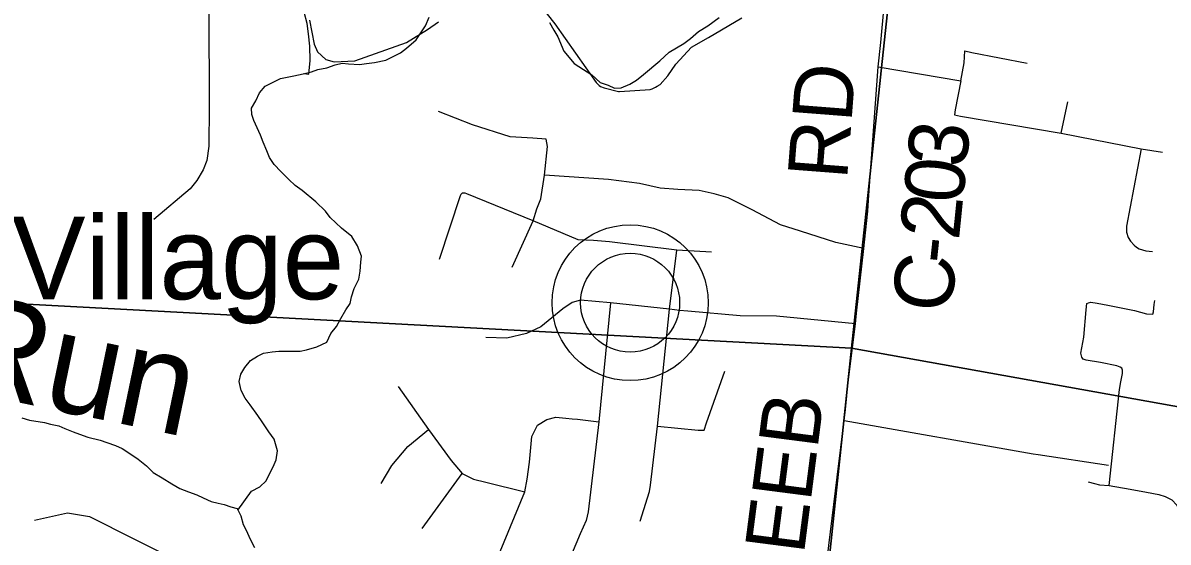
# Model space of a CAD drawing. Extents: x 0 to 34, y -2 to 22.
# Drawn here: x 3.329 to 4.421, y 16.731 to 17.226 of the extents above; entities that cross this region are included whole.
import ezdxf

# ---------------------------------------------------------------- set-up
doc = ezdxf.new("R2010")
doc.units = 0
for name, color, linetype in [('GM_X_County_Road', 7, 'Continuous'), ('GM_X_County_Road_Text', 7, 'Continuous'), ('GM_X_Minor_River', 7, 'Continuous'), ('GM_X_Minor_River_Text', 7, 'Continuous'), ('GM_X_Section', 7, 'Continuous'), ('GM_X_Township_Road', 7, 'Continuous'), ('GM_X_Unincorporated', 7, 'Continuous'), ('GM_X_Unincorporated_Location', 7, 'Continuous'), ('GM_X_Unincorporated_Text', 7, 'Continuous')]:
    doc.layers.add(name, color=color, linetype=linetype)

msp = doc.modelspace()

# ---------------------------------------------------------------- linework, layer by layer
at = {"layer": 'GM_X_County_Road'}
for points in [[(4.1357, 17.0618), (4.1445, 17.1843), (4.147, 17.2076), (4.1533, 17.2738), (4.1587, 17.295), (4.1597, 17.3001), (4.1595, 17.3027), (4.1576, 17.3113), (4.1539, 17.3349), (4.1534, 17.3381), (4.1533, 17.3414), (4.1555, 17.3542), (4.171, 17.4373), (4.1756, 17.4751), (4.1791, 17.5032), (4.188, 17.5731), (4.2018, 17.6987), (4.2231, 17.8563)], [(3.8216, 17.2439), (3.8364, 17.2254), (3.8757, 17.1695), (3.8786, 17.1664), (3.8799, 17.1655), (3.8832, 17.1644), (3.897, 17.1609), (3.8979, 17.1607), (3.9271, 17.1627), (3.9291, 17.1633), (3.9323, 17.1648), (3.934, 17.1658), (3.9366, 17.1674), (3.9441, 17.1756), (3.9516, 17.1868), (3.9667, 17.2032), (3.9828, 17.2123), (4.0147, 17.231)], [(3.6024, 17.2289), (3.6069, 17.2061), (3.6101, 17.1988), (3.6179, 17.1914), (3.6258, 17.189), (3.6456, 17.1901), (3.6949, 17.2076), (3.7149, 17.22), (3.7253, 17.2274)], [(4.124, 16.9493), (4.131, 17.0108), (4.1346, 17.0465), (4.1357, 17.0618)], [(4.1133, 16.8573), (4.1161, 16.8832), (4.1229, 16.9391), (4.124, 16.9493)], [(4.1005, 16.5212), (4.1022, 16.532), (4.1001, 16.5438), (4.0993, 16.5618), (4.0889, 16.5904), (4.086, 16.6037), (4.0848, 16.6181), (4.0856, 16.6343), (4.0959, 16.7145), (4.1054, 16.7928), (4.1122, 16.8469), (4.1133, 16.8573)], [(3.3401, 16.7515), (3.3717, 16.7585), (3.3928, 16.755), (3.4349, 16.7339), (3.463, 16.7199), (3.5016, 16.6918), (3.5297, 16.6777), (3.5648, 16.6742), (3.6105, 16.6742), (3.6518, 16.6741)]]:
    msp.add_lwpolyline(points, dxfattribs=at)
at = {"layer": 'GM_X_Minor_River'}
for points in [[(3.5342, 16.7612), (3.5471, 16.7792), (3.5552, 16.7836), (3.561, 16.7892), (3.5641, 16.7952), (3.5677, 16.8027), (3.5705, 16.8091), (3.5718, 16.8179), (3.5686, 16.8289), (3.5637, 16.8359), (3.5574, 16.8455), (3.5533, 16.8516), (3.5459, 16.8617), (3.541, 16.8682), (3.5374, 16.8755), (3.5352, 16.8839), (3.5369, 16.8911), (3.5408, 16.8975), (3.5463, 16.9039), (3.5529, 16.9083), (3.5586, 16.9109), (3.5667, 16.9122), (3.5732, 16.9129), (3.58, 16.9128), (3.5858, 16.913), (3.5934, 16.9129), (3.5995, 16.9143), (3.6095, 16.9172), (3.6188, 16.9216), (3.6227, 16.9299), (3.6282, 16.9366), (3.6322, 16.9441), (3.6369, 16.9524), (3.6412, 16.9584), (3.6425, 16.9649), (3.6449, 16.9728), (3.6493, 16.9818), (3.6506, 16.9894), (3.6515, 16.9978), (3.652, 17.0035), (3.6483, 17.0134), (3.6428, 17.0223), (3.633, 17.0304), (3.6221, 17.0405), (3.6176, 17.0467), (3.6086, 17.0556), (3.5954, 17.0664), (3.5887, 17.0711), (3.5827, 17.0769), (3.5752, 17.0843), (3.5688, 17.0912), (3.5643, 17.0978), (3.5618, 17.1043), (3.5581, 17.1123), (3.5556, 17.1192), (3.5493, 17.133), (3.5475, 17.1388), (3.5472, 17.1448), (3.5512, 17.152), (3.5548, 17.1595), (3.5602, 17.1659), (3.5683, 17.1699), (3.5749, 17.1732), (3.5875, 17.1757), (3.5963, 17.1778), (3.6044, 17.1796), (3.6105, 17.1817), (3.619, 17.1835), (3.627, 17.1864), (3.6336, 17.1878), (3.6397, 17.1873), (3.65, 17.1867), (3.6568, 17.1874), (3.6645, 17.1884), (3.6752, 17.1908), (3.6814, 17.1938), (3.6891, 17.1978), (3.6949, 17.2023), (3.7042, 17.2101), (3.7129, 17.2236), (3.7165, 17.2319)], [(3.5969, 17.1779), (3.6019, 17.1775), (3.603, 17.1904), (3.6026, 17.204), (3.6014, 17.2158), (3.6001, 17.2258), (3.5973, 17.2365)], [(3.8313, 17.2268), (3.8354, 17.2195), (3.8391, 17.213), (3.8449, 17.1992), (3.8547, 17.1876), (3.8637, 17.1818), (3.8716, 17.1767), (3.8795, 17.1693), (3.8871, 17.1669), (3.8932, 17.1641), (3.8997, 17.1644), (3.9078, 17.1677), (3.9143, 17.1717), (3.9209, 17.1769), (3.9364, 17.19), (3.9454, 17.1982), (3.9523, 17.2026), (3.9593, 17.2067), (3.9655, 17.2115), (3.9732, 17.2182), (3.9821, 17.2234), (3.9929, 17.2315)], [(3.328, 16.8492), (3.3356, 16.8472), (3.3497, 16.845), (3.3554, 16.8434), (3.3634, 16.8417), (3.369, 16.839), (3.377, 16.8358), (3.3831, 16.8338), (3.3911, 16.831), (3.4028, 16.8281), (3.4093, 16.8257), (3.4176, 16.8229), (3.4237, 16.8201), (3.4312, 16.8154), (3.4392, 16.81), (3.4471, 16.8034), (3.4534, 16.7972), (3.4621, 16.7921), (3.4712, 16.7862), (3.4788, 16.7819), (3.4871, 16.7787), (3.4951, 16.7759), (3.5011, 16.7731), (3.5087, 16.7696), (3.5152, 16.7679), (3.5212, 16.7667), (3.5273, 16.7643), (3.5334, 16.7627), (3.5371, 16.7558), (3.5392, 16.7474), (3.5422, 16.7416), (3.5455, 16.734), (3.5499, 16.7255)]]:
    msp.add_lwpolyline(points, dxfattribs=at)
at = {"layer": 'GM_X_Section'}
for points in [[(4.2197, 17.8557), (4.1192, 16.9159), (3.2017, 16.9647), (3.2914, 17.96)], [(5.25, 17.7471), (5.1427, 16.732), (4.1192, 16.9159), (4.2197, 17.8557)], [(4.1192, 16.9159), (4.012, 15.9002), (3.2406, 16.0402), (3.231, 16.0514), (3.2225, 16.0599), (3.2118, 16.0701), (3.2044, 16.0774), (3.197, 16.0844), (3.1881, 16.0918), (3.1769, 16.1008), (3.1658, 16.1098), (3.1569, 16.1176), (3.1469, 16.1266), (3.1398, 16.1328), (3.1309, 16.1402), (3.1283, 16.1422), (3.2017, 16.9647)], [(5.1427, 16.732), (5.0363, 15.7105), (4.012, 15.9002), (4.1192, 16.9159)]]:
    msp.add_lwpolyline(points, close=True, dxfattribs=at)
at = {"layer": 'GM_X_Township_Road'}
for p, q in [((4.3191, 17.1211), (4.3255, 17.151)), ((4.297, 16.8142), (4.3641, 16.804)), ((3.7097, 16.7438), (3.7479, 16.7962))]:
    msp.add_line(p, q, dxfattribs=at)
for points in [[(3.5217, 17.3039), (3.5106, 17.2961), (3.506, 17.2775), (3.506, 17.2627), (3.5063, 17.2381), (3.5067, 17.1462), (3.5065, 17.1086), (3.5046, 17.095), (3.5009, 17.0859), (3.4949, 17.0758), (3.4886, 17.068), (3.4541, 17.0387)], [(4.2235, 17.171), (4.2266, 17.1881), (4.2272, 17.1996), (4.2338, 17.1981), (4.2866, 17.1877)], [(4.1445, 17.1843), (4.2235, 17.171), (4.2179, 17.1432), (4.2173, 17.1384), (4.223, 17.1374), (4.3191, 17.1211), (4.3953, 17.1061), (4.4155, 17.1028)], [(3.7957, 16.993), (3.8157, 17.0374), (3.8192, 17.0488), (3.8228, 17.0584), (3.8263, 17.0809), (3.8292, 17.1083), (3.8281, 17.1154), (3.8153, 17.1161), (3.7936, 17.1175), (3.7577, 17.1289), (3.7253, 17.1417)], [(4.3953, 17.1061), (4.3813, 17.0322), (4.3814, 17.0265), (4.383, 17.0215), (4.385, 17.018), (4.3887, 17.014), (4.3909, 17.0123), (4.3935, 17.0105), (4.3996, 17.0087), (4.4062, 17.008)], [(4.131, 17.0108), (4.1043, 17.0168), (4.0705, 17.0275), (4.0516, 17.0334), (4.0244, 17.0479), (4.0017, 17.0593), (3.9881, 17.0632), (3.974, 17.0663), (3.9537, 17.0673), (3.9368, 17.0686), (3.9169, 17.073), (3.8874, 17.0768), (3.8263, 17.0809)], [(3.9856, 17.0074), (3.9525, 17.0095), (3.8883, 17.0172), (3.8731, 17.0186), (3.8584, 17.0193), (3.8157, 17.0374), (3.7524, 17.063), (3.7509, 17.0636), (3.7493, 17.0639), (3.748, 17.0636), (3.7467, 17.0625), (3.7459, 17.0612), (3.726, 17.0006)], [(3.9177, 16.7506), (3.9246, 16.7728), (3.9264, 16.779), (3.9276, 16.7851), (3.9342, 16.8415), (3.9456, 16.9529), (3.9525, 17.0095)], [(3.9553, 16.9518), (3.9456, 16.9529), (3.8895, 16.9592), (3.8609, 16.9615), (3.8528, 16.9593), (3.8438, 16.9535), (3.823, 16.9362), (3.8093, 16.9298), (3.7904, 16.9254), (3.7705, 16.9259)], [(3.8895, 16.9592), (3.8781, 16.8455), (3.8682, 16.7597), (3.8661, 16.7514), (3.8605, 16.7386), (3.8301, 16.6657)], [(4.3649, 16.7846), (4.3748, 16.8765), (4.3759, 16.8837), (4.3776, 16.8916), (4.3774, 16.8949), (4.377, 16.8966), (4.3754, 16.8977), (4.3722, 16.8988), (4.3564, 16.9021), (4.343, 16.9043), (4.3401, 16.9054), (4.3388, 16.9072), (4.3379, 16.9111), (4.3408, 16.9263), (4.343, 16.9524), (4.3436, 16.9583), (4.345, 16.9592), (4.3474, 16.9596), (4.3533, 16.9587), (4.3634, 16.9567), (4.389, 16.9517), (4.4005, 16.9486), (4.4064, 16.9482), (4.407, 16.9506), (4.4077, 16.9576), (4.4083, 16.9613)], [(4.1229, 16.9391), (4.0475, 16.9465), (4.013, 16.9467), (3.9632, 16.951), (3.9553, 16.9518)], [(3.9342, 16.8415), (3.9731, 16.8375), (3.9786, 16.8375), (3.981, 16.8446), (3.9984, 16.8939)], [(3.6869, 16.8791), (3.7159, 16.8381), (3.7376, 16.8085), (3.7479, 16.7962), (3.7589, 16.7907), (3.7706, 16.788), (3.8077, 16.7786)], [(3.7783, 16.707), (3.8077, 16.7786), (3.8098, 16.7908), (3.8123, 16.8069), (3.8144, 16.8314), (3.8198, 16.8423), (3.8288, 16.8476), (3.8374, 16.8499), (3.8468, 16.849), (3.8529, 16.8484)], [(3.8529, 16.8484), (3.8578, 16.848), (3.8781, 16.8455)], [(4.1122, 16.8469), (4.2923, 16.8149), (4.297, 16.8142)], [(3.6708, 16.7867), (3.6809, 16.8039), (3.6963, 16.8219), (3.7159, 16.8381)], [(4.3447, 16.7881), (4.3507, 16.7865), (4.3557, 16.7854), (4.3649, 16.7846), (4.3847, 16.7811), (4.4005, 16.7784), (4.4121, 16.7762), (4.4182, 16.7743), (4.4244, 16.7712), (4.4292, 16.7661), (4.4344, 16.753), (4.4369, 16.7431), (4.4384, 16.7346), (4.4364, 16.7269), (4.4351, 16.7205), (4.4358, 16.7122), (4.4382, 16.7085), (4.4407, 16.704)]]:
    msp.add_lwpolyline(points, dxfattribs=at)
at = {"layer": 'GM_X_Unincorporated'}
for radius in [0.0744, 0.0472]:
    msp.add_circle((3.9081, 16.9592), radius, dxfattribs=at)
at = {"layer": 'GM_X_Unincorporated_Location'}
msp.add_line((3.9081, 16.9592), (3.9081, 16.9592), dxfattribs=at)

# ---------------------------------------------------------------- texts
at = {"layer": 'GM_X_County_Road_Text'}
for s, height, rotation, p in [('RD', 0.05682, 85.5636, (4.1148, 17.0759)), ('3', 0.0568, 84.3504, (4.2284, 17.0872)), ('0', 0.0568, 84.3347, (4.225, 17.0527)), ('2', 0.0568, 84.2643, (4.2215, 17.018)), ('-', 0.0568, 83.9301, (4.219, 16.9947)), ('C', 0.0568, 83.5847, (4.2138, 16.9483)), ('NEEB', 0.05682, 82.6474, (4.0666, 16.6636))]:
    msp.add_text(s, height=height, rotation=rotation, dxfattribs=at).set_placement(p)
at = {"layer": 'GM_X_Minor_River_Text'}
msp.add_text('Run', height=0.0947, rotation=348.2363, dxfattribs=at).set_placement((3.2559, 16.8784))
at = {"layer": 'GM_X_Unincorporated_Text'}
msp.add_text('Cotillion Village', height=0.078977, rotation=0, dxfattribs=at).set_placement((2.9135, 16.9625))

doc.saveas('drawing.dxf')
